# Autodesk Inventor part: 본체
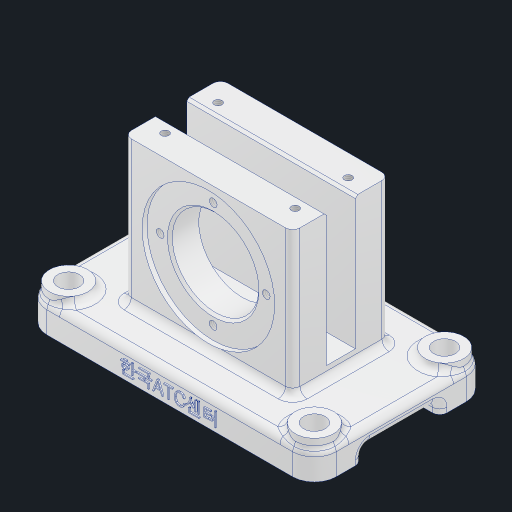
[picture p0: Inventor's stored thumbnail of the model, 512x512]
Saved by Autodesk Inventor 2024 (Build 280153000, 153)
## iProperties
Created: 2025-04
Part Number: 본체
Material: 알루미늄 6061
Document SubType Name: Modeling
Designer: kh_501
Density: 2.7 g/cm^3
Appearance: 알루미늄 - 평지
Mass: 493.658 g
Surface Area: 439.689 cm^2
Volume: 182.836 cm^3
Author: kh_501
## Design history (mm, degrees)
sketch "스케치1"
  geometry: L1 (-36, 60)-(36, 60); L2 (36, 60)-(36, -60); L3 (36, -60)-(-36, -60); L4 (-36, -60)-(-36, 60); L5 (-36, 60)-(36, -60); L6 (36, 60)-(-36, -60); L7 (-27, 51)-(27, 51); L8 (27, 51)-(27, -51); L9 (27, -51)-(-27, -51); L10 (-27, -51)-(-27, 51); L11 (-27, 51)-(27, -51); L12 (27, 51)-(-27, -51); C1 r 8 at (27, 51); C2 r 8 at (-27, 51); C3 r 8 at (27, -51); C4 r 8 at (-27, -51); 1 further point
  constraints: 24 end point, 4 centre point, 4 coincident, 4 midpoint, 4 parallel, 2 horizontal, 2 perpendicular
  dimensions: "d0" = 120 distance of L1.end L2.end; "d1" = 72 distance of L2.end L3.end; "d2" = 102 distance of L7.end L8.end; "d3" = 54 distance of L8.end L9.end; "d4" = 16 diameter of C1; "d5" = 16 diameter of C2; "d6" = 16 diameter of C3; "d7" = 16 diameter of C4
extrude "돌출1" new body sketch "스케치1" distance "d8" = 12; taper "d9" = 0 deg
extrude "돌출2" join sketch "스케치1" distance "d10" = 15; taper "d11" = 0 deg
sketch "스케치2"
  geometry: C1 r 8 at (0, 0) reference; C2 r 8 at (54, 0) reference; C3 r 8 at (0, 102) reference; C4 r 8 at (54, 102) reference; 5 further points
  constraints: 4 coincident
hole "구멍1" sketch "스케치2" at (0, 0), (54, 0), (0, 102), (54, 102) diameter "d12" = 9; stored, may be unused: countersink angle "d16" = 90 deg, drill point angle "d18" = 118 deg; dims "d13" = 6, "d14" = 18, "d15" = 2, "d17" = 8
sketch "스케치3"
  geometry: L1 (-36, 12)-(36, 12) reference; L2 (-20, 12)-(-20, 72); L3 (-20, 72)-(-6, 72); L4 (-6, 72)-(-6, 17); L5 (-6, 17)-(6, 17); L6 (6, 17)-(6, 72); L7 (6, 72)-(20, 72); L8 (20, 72)-(20, 12); L9 (0, 17)-(0, 0); L10 (36, 0)-(-36, 0) reference; L11 (-16, 0)-(16, 0); L12 (16, 0)-(16, 5); L13 (16, 5)-(-16, 5); L14 (-16, 5)-(-16, 0); L15 (-16, 0)-(16, 5); L16 (16, 0)-(-16, 5); 4 further points
  constraints: 28 end point, 7 perpendicular, 5 midpoint, 5 point on line, 2 parallel, 1 horizontal, 1 vertical, 1 vertical alignment, 1 other
  dimensions: "d19" = 12 distance between parallel lines of L6 L4; "d20" = 40 distance between parallel lines of L8 L2; "d22" = 32 distance of L12.end L13.end; "d23" = 5 distance of L11.end L12.end; "d24" = 55 distance between parallel lines of L7 L5; "d25" = 72 distance between parallel lines of L3 L10
extrude "돌출3" cut sketch "스케치3" extent not by distance; stored distance "d26" = 0; taper "d27" = 0 deg
extrude "돌출4" join sketch "스케치3" stored distance "d28" = 70; taper "d29" = 0 deg
sketch "스케치4"
  geometry: L1 (-30.631, 42)-(37.503, 42); L2 (16, 0)-(36, 0) reference; L3 (-20, 72)-(-20, 12) reference; L4 (20, 12)-(20, 72) reference; L5 (-20, 69.5)-(-18, 69.5); L6 (-18, 69.5)-(-18, 60); L7 (6, 17)-(6, 72) reference; L8 (6, 72)-(20, 72) reference; L9 (20, 72)-(20, 12) reference; L10 (-20, 12)-(20, 12) reference; L11 (-20, 12)-(-20, 72) reference; L12 (-20, 72)-(-6, 72) reference; L13 (-6, 72)-(-6, 17) reference; L14 (-6, 17)-(6, 17) reference; L15 (-18, 60)-(-6, 60); L16 (6, 57)-(11, 57); L17 (11, 57)-(11, 53); L18 (20, 59)-(27, 59); L19 (27, 59)-(27, 42); L20 (11, 53)-(27, 53); 6 further points
  constraints: 18 end point, 6 perpendicular, 6 point on line, 3 horizontal
  dimensions: "d30" = 42 distance between parallel lines of L1 L2; "d31" = 5 distance of L16.start L16.end; "d32" = 30 diameter of L16 L1; "d33" = 22 diameter of L20 L1; "d34" = 36 diameter of L15 L1; "d35" = 55 diameter of L5 L1; "d36" = 2 distance of L5.start L5.end; "d37" = 7 distance of L18.start L18.end; "d38" = 34 diameter of L18 L1
  node "투영된 루프1"
revolve "회전1" stored, may be unused: angle "d39" = 90 deg
revolve "회전2" stored, may be unused: angle "d40" = 90 deg
sketch "스케치5"
  geometry: L1 (0, 0)-(0, 70) reference; L2 (14, 0)-(0, 0) reference; L3 (14, 70)-(14, 0) reference; L4 (0, 70)-(14, 70) reference; L5 (-26, 70)-(-26, 0) reference; L6 (-12, 0)-(-26, 0) reference; L7 (-12, 70)-(-12, 0) reference; L8 (-26, 70)-(-12, 70) reference; L9 (-17, 62)-(5, 62); L10 (5, 62)-(5, 8); L11 (5, 8)-(-17, 8); L12 (-17, 8)-(-17, 62); L13 (-17, 62)-(5, 8); L14 (5, 62)-(-17, 8); 5 further points
  constraints: 12 end point, 4 coincident, 2 midpoint, 2 parallel, 1 horizontal, 1 perpendicular
  dimensions: "d41" = 54 distance of L9.end L10.end; "d42" = 22 distance of L10.end L11.end
hole "구멍2" sketch "스케치5" at (5, 62), (-17, 62), (5, 8), (-17, 8) diameter "d43" = 3.242; stored, may be unused: countersink angle "d47" = 90 deg, drill point angle "d49" = 118 deg; dims "d44" = 8, "d45" = 4, "d46" = 2, "d48" = 10
sketch "스케치6" dims "d50" = 44
  geometry: L1 (0, 0)-(0, 22); C1 r 27.5 at (0, 0) reference; C2 r 18 at (0, 0) reference; 2 further points
  constraints: 2 coincident, 2 end point, 1 vertical, 1 vertical alignment, 2 other
hole "구멍3" sketch "스케치6" at (0, 22) diameter "d51" = 3.242; stored, may be unused: countersink angle "d55" = 90 deg, drill point angle "d57" = 118 deg; dims "d52" = 8, "d53" = 4, "d54" = 2, "d56" = 10
fillet "모깎기1" dims "d61" = 9
fillet "모깎기3" dims "d63" = 3
fillet "모깎기4" dims "d64" = 3
sketch "스케치7" dims "d0" = 120, "d1" = 72
  geometry: L1 (0, 0)-(102, 0) reference; 3 further points
  constraints: 1 midpoint, 1 vertical alignment, 1 other
  dimensions: "d65" = 5 distance from line of point (51, 5) L1
feature "엠보싱1" sketch "스케치7" dims "d0" = 120, "d1" = 72, "d66" = 0.5, "d67" = 0
fillet "모깎기5" dims "d68" = 3
fillet "모깎기6" dims "d69" = 3
fillet "모깎기8" dims "d71" = 3
fillet "모깎기9" dims "d72" = 3
chamfer "모따기1" distance "d73" = 1; stored, may be unused: second distance "d74" = 2, angle "d75" = 45 deg
chamfer "모따기2" distance "d76" = 1; stored, may be unused: second distance "d77" = 2, angle "d78" = 45 deg
fillet "모깎기10" dims "d79" = 3
node "솔리드1"
pattern_circular "원형 패턴1" dims angle "d59" = 360 deg
node "투영된 루프2"
node "투영된 루프3"
node "투영된 루프4"
feature "A9D066F2-1C7D-4E18-AEED-F7BC21143FA4" dims "d12" = 9, "d13" = 6, "d14" = 18, "d15" = 2, "d16" = 90 deg, "d17" = 8, "d18" = 118 deg
